(* Logix 5000 project; controller Test vendor 1 type 14 code 92 rev 33.11; software revision 33.00 *)

TASK MainTask (continuous, watchdog 500 ms) : MainProgram

MODULES
   Local : vendor 1 type 14 code 92 (ICP 0, rev 33.11)
      IN : vendor 1 type 7 code 1 (ICP 3, rev 3.2, Input RPI 20 ms)
      O : vendor 1 type 7 code 15 (ICP 2, rev 3.2, Output RPI 20 ms)
      Ethernet : 1756-ENBT (ICP 1, Ethernet 192.168.0.98, rev 6.4)
         IOLM1 : DXM (Ethernet 192.168.0.1, rev 2.22, StandardDataDriven RPI 20 ms)
END_MODULES

TYPE Banner_IOL_Port_v4 :   // UDT that has all of the data items necessary to communicate with a specific Port on a IO-Link Master
STRUCT
   Port_Controlled : INT;   // Each bit represents a port on an IO-Link Master. Set to 1 to tell AOI to control that port.
   Port_Activate : INT;   // Each bit represents a port on an IO-Link Master. When ON that port will process any commands in queue.
   Port_Read : INT;   // Each bit represents a port on an IO-Link Master. Used to determine when device AOI has requested a Read command.
   Port_Write : INT;   // Each bit represents a port on an IO-Link Master. Used to determine when device AOI has requested a Write command.
   Port_RW_Complete : INT;   // Each bit represents a port on an IO-Link Master. Tells device AOI that Read or Write request has been completed.
   Port_Device_Read : INT;
   Data_Transfer : SINT[190];   // Array to transfer data from IO-Master to device AOIs.
END_STRUCT
END_TYPE

TYPE Banner_IOLM_EL_v2 :   // Error Log for Messages to IOLM.
STRUCT
   RW : SINT;   // 0 = Read, 1 = Write.
   Port : SINT;   // Port number that generated error.
   Index : INT;   // IO-Link Index for generated error.
END_STRUCT
END_TYPE

TYPE Banner_IOLM_v4 :   // UDT to control IO-Link Masters.
STRUCT
   Message_Source_Data : SINT[190];
   Message_Destination_Data : SINT[190];
   Error_Log : Banner_IOLM_EL_v2[10];
   Error_Write_Retry : BOOL;
   Num_Error_MSGS : DINT;
   IO_Link_Master_Busy : BOOL;   // 0 = While waiting for a command, 1 = Processing command
   AOI_Reset : BOOL;
   Port_Data : Banner_IOL_Port_v4;   // All of the necessary data to work with the various ports of the IO-Link Master.
   Halt_Operation : BOOL;   // When parameter is 1 the AOI is halted as next available time frame.
   AOI_Halted : BOOL;   // AOI is in standby mode until Halt Operation tag is set back to 0.
END_STRUCT
END_TYPE

TYPE Banner_K50Z_BDC_v4 :   // All of the BDC data for channels 1 and 2.
STRUCT
   SP1 : DINT;   // Switchpoint.
   SP2 : DINT;   // In 2pt window mode, defines the second switching point. In other modes, SP2 is unused and must be 0.
   Switchpoint_Logic : SINT;   // 0 = Light operate, 1 = Dark operate
   BDC_Mode : INT;   // 1 = 1pt Object Set, 128 = 2pt static BGS, 129 = 2pt Window FGS, 130 = 1pt Window FGS, 131 = Dual Mode.
   Hysteresis : INT;   // A value of 0 will result in automatically calculated hysteresis.
   Delay_Mode : SINT;   // 0 = Disabled, 1 = On Off Delay, 2 = Oneshot.
   Delay_Time_On_Oneshot : DINT;   // 0 to 90000. On delay and oneshot time.
   Delay_Time_Off : DINT;   // 0 to 90000. Off delay only.
   Teach_Offset : SINT;   // 0 = Auto, 1 = User Selected
   User_Teach_Offset : DINT;   // In Object Set or Window (FGS) mode this value can be either positive or negative. In all other modes must be zero.
END_STRUCT
END_TYPE

TYPE Banner_K50Z_PD0_v4 :   // Process Data 0 for a K50Z.
STRUCT
   C1_Output_State : SINT;   // 0 = Inactive, 1 = Active
   C2_Output_State : SINT;   // 0 = Inactive, 1 = Active
   Stability_Z1 : SINT;   // 0 = No target or Marginal, 1 = Stable
   Stability_Z2 : SINT;   // 0 = No target or Marginal, 1 = Stable
   Measurement_1 : DINT;   // Default setting is Measurement Value for Zone 1. See IODD for all options.
   Measurement_2 : DINT;   // Default setting is Measurement Value for Zone 2. See IODD for all options.
END_STRUCT
END_TYPE

TYPE Banner_K50Z_PD1_v4 :   // Process Data 1 for a K50Z.
STRUCT
   Measurement_1 : DINT;   // Default setting is Measurement Value for Zone 1. See IODD for all options.
   Measurement_2 : DINT;   // Default setting is Measurement Value for Zone 2. See IODD for all options.
END_STRUCT
END_TYPE

TYPE Banner_K50Z_PD2_v4 :   // Process Data 2 for a K50Z.
STRUCT
   Measurement : DINT;   // Measurement Value
   Measure_Scale : DINT;   // Scale Factor for Measurement
   Stability : SINT;   // 0 = Inactive 1 = Active
   Channel_1 : SINT;   // 0 = Inactive 1 = Active
   Channel_2 : INT;   // 0 = Inactive 1 = Active
END_STRUCT
END_TYPE

TYPE Banner_K50Z_PDIO_v4 :   // Process Data for a K50Z.
STRUCT
   PDI_0 : Banner_K50Z_PD0_v4;   // Input Procoess Data for Configuration 0
   PDI_1 : Banner_K50Z_PD1_v4;   // Input Procoess Data for Configuration 1
   PDI_2 : Banner_K50Z_PD2_v4;   // Input Procoess Data for Configuration 2
   Emitter_Disable : SINT;   // 0 = Active 1 = Inactive
   PDI_DT : SINT[4];
END_STRUCT
END_TYPE

TYPE Banner_K50Z_Pulse_Freq_v4 :
STRUCT
   Near_Freq : DINT;   // 1 to 100000 in Hz
   Far_Freq : DINT;   // 1 to 100000 in Hz
   SP1 : DINT;   // Switchpoint
   SP2 : DINT;   // In 2pt Window FGS teach, define the second switching point. In other modes SP2 should be zero.
   Pulse_Freq_LOS : DINT;   // Default value of 50. This is the Hz that the units outputs when a Loss of Signal occurs.
END_STRUCT
END_TYPE

TYPE Banner_K50Z_RD_v4 :   // UDT that stores the Write Data for a K50Z.
STRUCT
   Master_Cycle_Time : INT;
   Min_Cycle_Time : INT;
   M_Sequence_Capability : INT;
   IO_Link_Version_ID : INT;
   Process_Data_Input_Length : INT;
   Process_Data_Output_Length : INT;
   Combined_Vendor_ID : DINT;   // IO-Link Vendor ID
   Vendor_ID1 : INT;
   Vendor_ID2 : INT;
   Combined_Device_ID : DINT;   // IO-Link Device ID
   Device_ID1 : INT;
   Device_ID2 : INT;
   Device_ID3 : INT;
   Serial_Number : STRING;
   Teach_State : SINT;   // 0=Idle, 1=SP1 Success, 4=Wait for Command, 5=Busy, 7=Error.
   SP1_TP1 : SINT;
   SP1_TP2 : SINT;
   Measurement_Z1 : DINT;
   Excess_Gain_Z1 : DINT;   // Amount of singal measured over the minimum threshold.
   Stability_Z1 : SINT;   // 0=No target exists, 1=Marginal signal, 2=Stable.
   Measurement_Z2 : DINT;
   Excess_Gain_Z2 : DINT;   // Amount of singal measured over the minimum threshold.
   Stability_Z2 : SINT;   // 0=No target exists, 1=Marginal signal, 2=Stable.
   Emitter_Status : SINT;   // 0 = Active, 1 = Inactive
   Temperature : DINT;   // Internal temperature measurement for the device.
   Last_Taught_Temperature : DINT;   // Internal Temperature the last time device was taught.
   MDC_Lower_Limit : DINT;
   MDC_Upper_Limit : DINT;
   MDC_Unit : INT;
   MDC_Scale : SINT;
END_STRUCT
END_TYPE

TYPE Banner_K50Z_v4 :   // All of the parameters for a K50Z.
STRUCT
   Initial_Global_Read : BOOL;   // Determines if all of the IO-Link data has been read into the PLC yet
   Command : INT;   // Value placed in here will activate a read or write to a specifc IO-Link Index
   Read : Banner_K50Z_RD_v4;   // Read Only Data
   Write : Banner_K50Z_WD_v4;   // Write Data
   Archive : Banner_K50Z_WD_v4;   // Archive Data
   Reset : BOOL;   // Resets AOI. This will force a complete parameter read of the sensor.
END_STRUCT
END_TYPE

TYPE Banner_K50Z_WD_v4 :   // UDT that stores the Write Data for a K50Z.
STRUCT
   System_Command : INT;   // See IODD file for list of commands that can be activated via the System Command interface
   Parameter_Access_Lock : SINT;   // Write access to all parameters is prohibited while value is 1. Only this parameter can be adjusted when value is 1.
   Data_Storage_Lock : SINT;   // Automatic data storage is disabled when this value is equal to 1. Read access is not affected.
   Local_Parameterization_Lock : SINT;   // Parameterization via local control elements on device is disabled.
   Local_User_Interface_Lock : SINT;   // Operation of local user interface is disabled.
   Teach_Channel : SINT;   // 0 = Default, 1 = BDC1, 2 = BDC2
   Response_Speed : SINT;   // 0 = Speed 0, 1 = Speed 1, 2 = Speed 2, 3 = Speed 3
   Remote_Input_Mode : SINT;   // 0 = Remote Teach Input, 1 = Emitter On, 2 = Emitter Off
   Secondary_Output_Mode : SINT;   // 0 = Independent Output, 1 = Complementary Output, 2 = Pulse Frequency Output
   IOL_Filter_Time : INT;   // Time to average IOl process data measurement between updates
   Include_Binary : SINT;   // 0 = Include, 1 = Don't Include, 2= Measurement Device
   Measurement_1 : SINT;   // 0 = Disabled, 1 = Excess Gain Z1, 2 = Excess Gain Z2, 3 = Excess Gain / 10 Z1, 4 = Excess Gain / 10 Z2, 5 = Measurement Z1, 6 = Measurement Z2.
   Measurement_2 : SINT;   // 0 = Disabled, 1 = Excess Gain Z1, 2 = Excess Gain Z2, 3 = Excess Gain / 10 Z1, 4 = Excess Gain / 10 Z2, 5 = Measurement Z1, 6 = Measurement Z2.
   Digital_Measuring_Sensor_Zone_Selection : SINT;   // 0=Zone 1, 1=Zone2
   BDC : Banner_K50Z_BDC_v4[3];
   Pulse_Freq : Banner_K50Z_Pulse_Freq_v4;
END_STRUCT
END_TYPE

ADD_ON_INSTRUCTION Banner_DXMR90_IOLM_v4   (* revision 4.1, vendor Banner Engineering *)
// AOI that controls a Banner IO-Link Master with Banner devices.
// Revision note:
// Revised operational order for ISDU write.
VAR_IN_OUT
   IOLM : Banner_IOLM_v4; {required}
END_VAR
VAR
   Lock : DINT; {access None}
   Byte_Length : SINT; {access None}
   Current_Port : INT; {access None}   // Current port to communicate with via the IO-Link Master.
   Timer : TIMER := (PRE := 500); {access None}
   Error_Index : DINT; {access None}
   Timer2 : TIMER := (PRE := 5000); {access None}
   Temp_Index : INT; {access None}
   ErrCount : DINT; {access None}
   Timer4 : TIMER := (PRE := 2000); {access None}
   Timer5 : TIMER := (PRE := 2000); {access None}
   Timer3 : TIMER := (PRE := 2000); {access None}
   Timer6 : TIMER := (PRE := 3000); {access None}
   Timer7 : TIMER := (PRE := 3000); {access None}
END_VAR

ROUTINE Logic   (* ladder *)
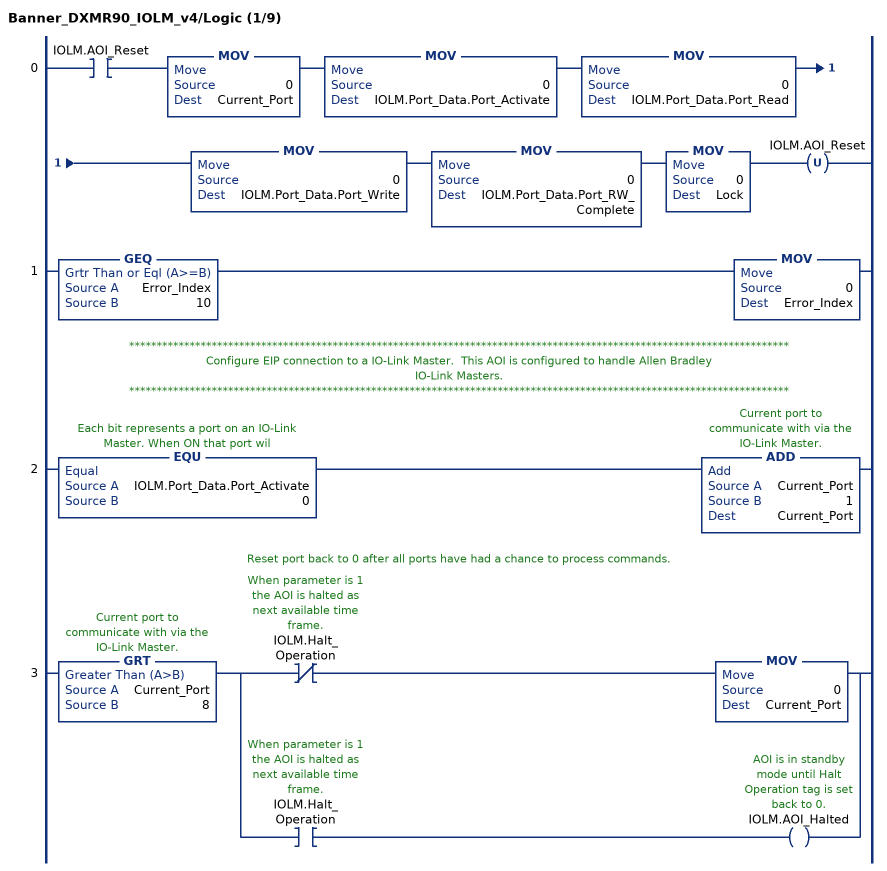
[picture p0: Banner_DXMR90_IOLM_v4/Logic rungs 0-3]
   0: XIC(IOLM.AOI_Reset)MOV(0,Current_Port)MOV(0,IOLM.Port_Data.Port_Activate)MOV(0,IOLM.Port_Data.Port_Read)MOV(0,IOLM.Port_Data.Port_Write)MOV(0,IOLM.Port_Data.Port_RW_Complete)MOV(0,Lock)OTU(IOLM.AOI_Reset);
   1: GEQ(Error_Index,10)MOV(0,Error_Index);
   // ************************************************************************************************************************
   // Configure EIP connection to a IO-Link Master.  This AOI is configured to handle Allen Bradley
   // IO-Link Masters.
   // ************************************************************************************************************************
   2: EQU(IOLM.Port_Data.Port_Activate,0)ADD(Current_Port,1,Current_Port);
   // Reset port back to 0 after all ports have had a chance to process commands.
   3: GRT(Current_Port,8)[XIO(IOLM.Halt_Operation) MOV(0,Current_Port) ,XIC(IOLM.Halt_Operation) OTE(IOLM.AOI_Halted) ];
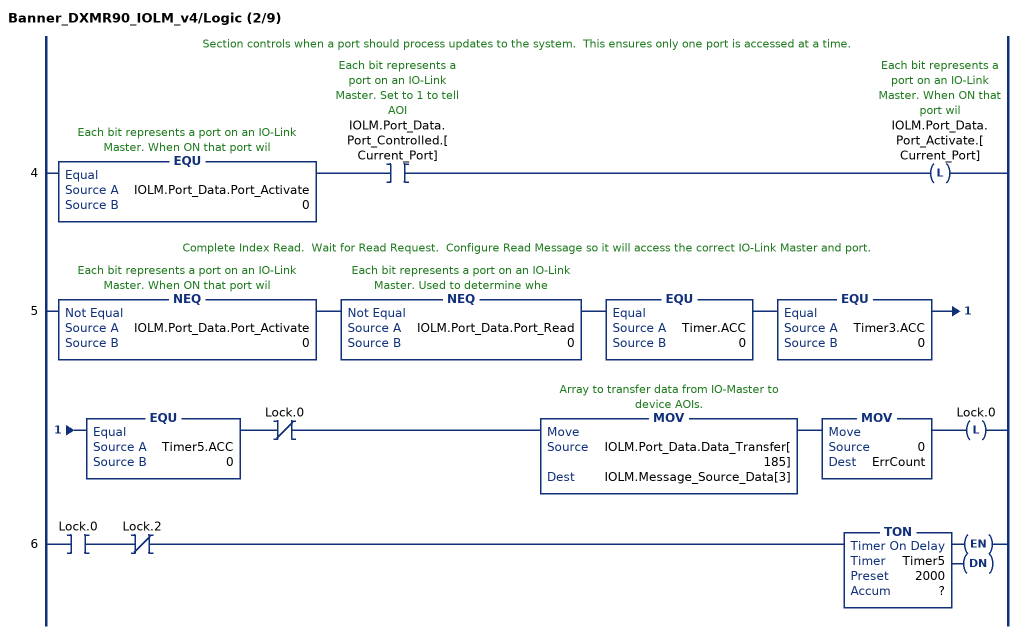
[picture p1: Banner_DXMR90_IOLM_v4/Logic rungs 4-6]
   // Section controls when a port should process updates to the system.  This ensures only one port is accessed at a time.
   4: EQU(IOLM.Port_Data.Port_Activate,0)XIC(IOLM.Port_Data.Port_Controlled.[Current_Port])OTL(IOLM.Port_Data.Port_Activate.[Current_Port]);
   // Complete Index Read.  Wait for Read Request.  Configure Read Message so it will access the correct IO-Link Master and port.
   5: NEQ(IOLM.Port_Data.Port_Activate,0)NEQ(IOLM.Port_Data.Port_Read,0)EQU(Timer.ACC,0)EQU(Timer3.ACC,0)EQU(Timer5.ACC,0)XIO(Lock.0)MOV(IOLM.Port_Data.Data_Transfer[185],IOLM.Message_Source_Data[3])MOV(0,ErrCount)OTL(Lock.0);
   6: XIC(Lock.0)XIO(Lock.2)TON(Timer5,?,?);
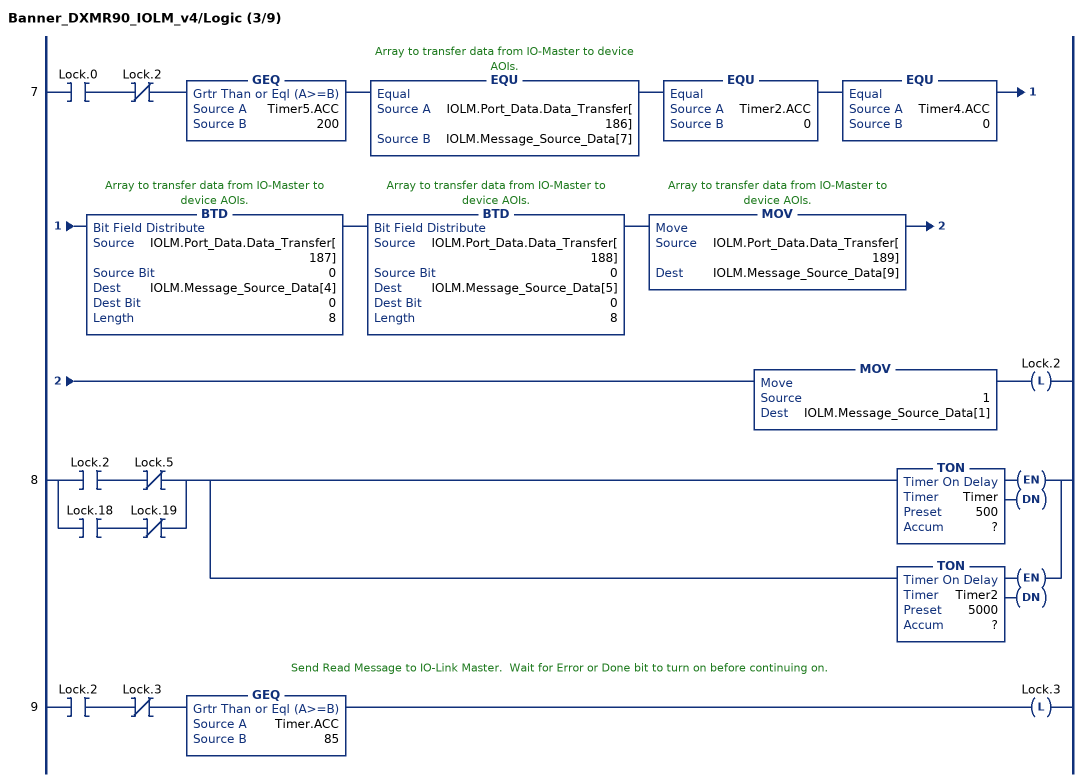
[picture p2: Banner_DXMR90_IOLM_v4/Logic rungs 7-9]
   7: XIC(Lock.0)XIO(Lock.2)GEQ(Timer5.ACC,200)EQU(IOLM.Port_Data.Data_Transfer[186],IOLM.Message_Source_Data[7])EQU(Timer2.ACC,0)EQU(Timer4.ACC,0)BTD(IOLM.Port_Data.Data_Transfer[187],0,IOLM.Message_Source_Data[4],0,8)BTD(IOLM.Port_Data.Data_Transfer[188],0,IOLM.Message_Source_Data[5],0,8)MOV(IOLM.Port_Data.Data_Transfer[189],IOLM.Message_Source_Data[9])MOV(1,IOLM.Message_Source_Data[1])OTL(Lock.2);
   8: [XIC(Lock.2) XIO(Lock.5) ,XIC(Lock.18) XIO(Lock.19) ][TON(Timer,?,?) ,TON(Timer2,?,?) ];
   // Send Read Message to IO-Link Master.  Wait for Error or Done bit to turn on before continuing on.
   9: XIC(Lock.2)XIO(Lock.3)GEQ(Timer.ACC,85)OTL(Lock.3);
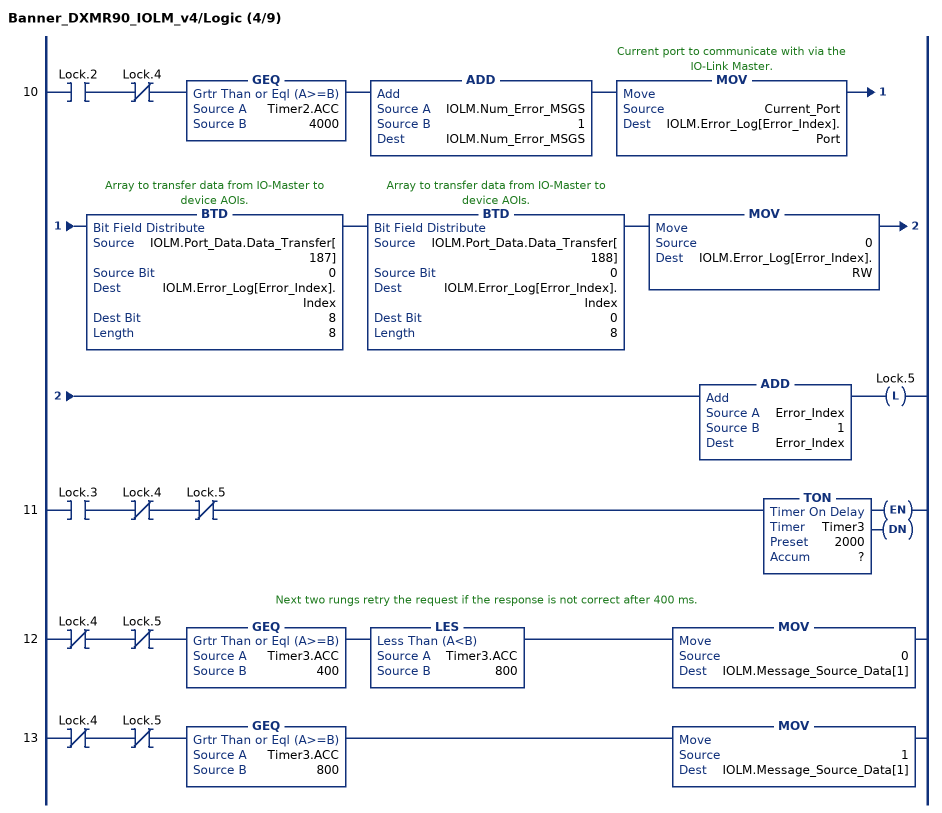
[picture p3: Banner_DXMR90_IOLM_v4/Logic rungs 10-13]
   10: XIC(Lock.2)XIO(Lock.4)GEQ(Timer2.ACC,4000)ADD(IOLM.Num_Error_MSGS,1,IOLM.Num_Error_MSGS)MOV(Current_Port,IOLM.Error_Log[Error_Index].Port)BTD(IOLM.Port_Data.Data_Transfer[187],0,IOLM.Error_Log[Error_Index].Index,8,8)BTD(IOLM.Port_Data.Data_Transfer[188],0,IOLM.Error_Log[Error_Index].Index,0,8)MOV(0,IOLM.Error_Log[Error_Index].RW)ADD(Error_Index,1,Error_Index)OTL(Lock.5);
   11: XIC(Lock.3)XIO(Lock.4)XIO(Lock.5)TON(Timer3,?,?);
   // Next two rungs retry the request if the response is not correct after 400 ms.
   12: XIO(Lock.4)XIO(Lock.5)GEQ(Timer3.ACC,400)LES(Timer3.ACC,800)MOV(0,IOLM.Message_Source_Data[1]);
   13: XIO(Lock.4)XIO(Lock.5)GEQ(Timer3.ACC,800)MOV(1,IOLM.Message_Source_Data[1]);
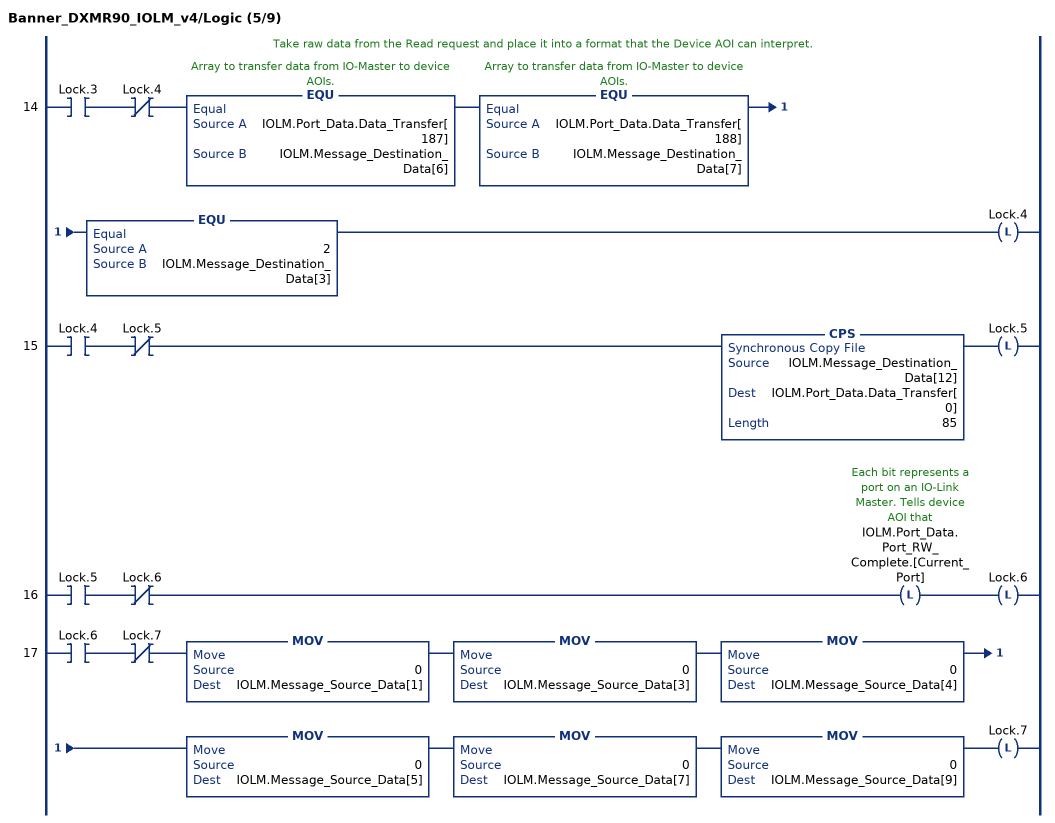
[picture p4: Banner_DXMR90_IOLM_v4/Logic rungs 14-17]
   // Take raw data from the Read request and place it into a format that the Device AOI can interpret.
   14: XIC(Lock.3)XIO(Lock.4)EQU(IOLM.Port_Data.Data_Transfer[187],IOLM.Message_Destination_Data[6])EQU(IOLM.Port_Data.Data_Transfer[188],IOLM.Message_Destination_Data[7])EQU(2,IOLM.Message_Destination_Data[3])OTL(Lock.4);
   15: XIC(Lock.4)XIO(Lock.5)CPS(IOLM.Message_Destination_Data[12],IOLM.Port_Data.Data_Transfer[0],85)OTL(Lock.5);
   16: XIC(Lock.5)XIO(Lock.6)OTL(IOLM.Port_Data.Port_RW_Complete.[Current_Port])OTL(Lock.6);
   17: XIC(Lock.6)XIO(Lock.7)MOV(0,IOLM.Message_Source_Data[1])MOV(0,IOLM.Message_Source_Data[3])MOV(0,IOLM.Message_Source_Data[4])MOV(0,IOLM.Message_Source_Data[5])MOV(0,IOLM.Message_Source_Data[7])MOV(0,IOLM.Message_Source_Data[9])OTL(Lock.7);
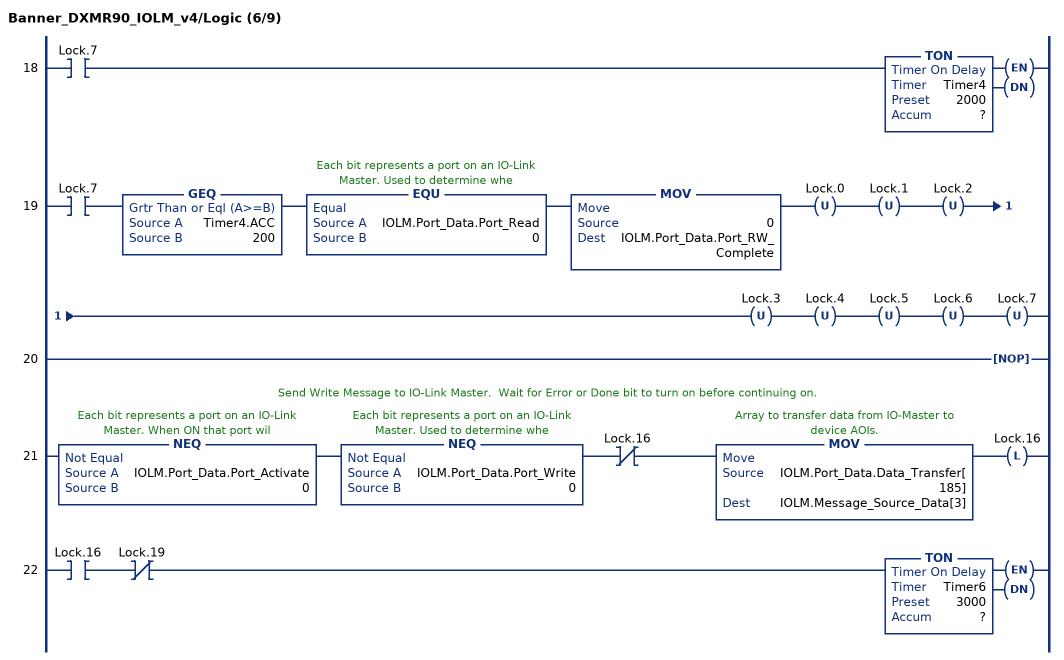
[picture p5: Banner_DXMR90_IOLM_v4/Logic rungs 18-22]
   18: XIC(Lock.7)TON(Timer4,?,?);
   19: XIC(Lock.7)GEQ(Timer4.ACC,200)EQU(IOLM.Port_Data.Port_Read,0)MOV(0,IOLM.Port_Data.Port_RW_Complete)OTU(Lock.0)OTU(Lock.1)OTU(Lock.2)OTU(Lock.3)OTU(Lock.4)OTU(Lock.5)OTU(Lock.6)OTU(Lock.7);
   20: NOP();
   // Send Write Message to IO-Link Master.  Wait for Error or Done bit to turn on before continuing on.
   21: NEQ(IOLM.Port_Data.Port_Activate,0)NEQ(IOLM.Port_Data.Port_Write,0)XIO(Lock.16)MOV(IOLM.Port_Data.Data_Transfer[185],IOLM.Message_Source_Data[3])OTL(Lock.16);
   22: XIC(Lock.16)XIO(Lock.19)TON(Timer6,?,?);
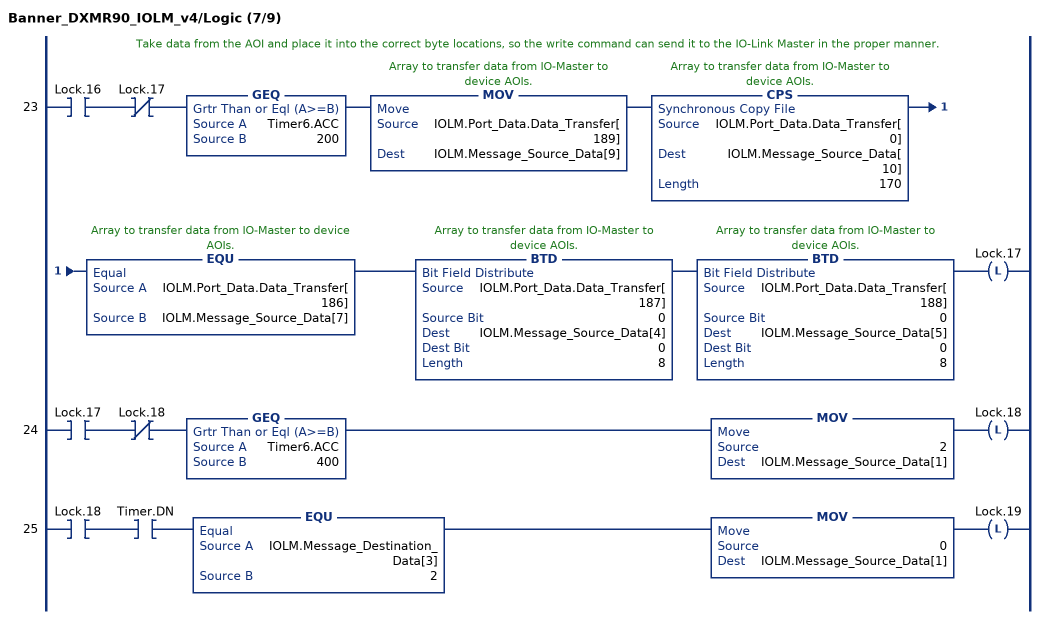
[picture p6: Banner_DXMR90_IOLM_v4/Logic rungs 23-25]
   // Take data from the AOI and place it into the correct byte locations, so the write command can send it to the IO-Link Master in the proper manner.
   23: XIC(Lock.16)XIO(Lock.17)GEQ(Timer6.ACC,200)MOV(IOLM.Port_Data.Data_Transfer[189],IOLM.Message_Source_Data[9])CPS(IOLM.Port_Data.Data_Transfer[0],IOLM.Message_Source_Data[10],170)EQU(IOLM.Port_Data.Data_Transfer[186],IOLM.Message_Source_Data[7])BTD(IOLM.Port_Data.Data_Transfer[187],0,IOLM.Message_Source_Data[4],0,8)BTD(IOLM.Port_Data.Data_Transfer[188],0,IOLM.Message_Source_Data[5],0,8)OTL(Lock.17);
   24: XIC(Lock.17)XIO(Lock.18)GEQ(Timer6.ACC,400)MOV(2,IOLM.Message_Source_Data[1])OTL(Lock.18);
   25: XIC(Lock.18)XIC(Timer.DN)EQU(IOLM.Message_Destination_Data[3],2)MOV(0,IOLM.Message_Source_Data[1])OTL(Lock.19);
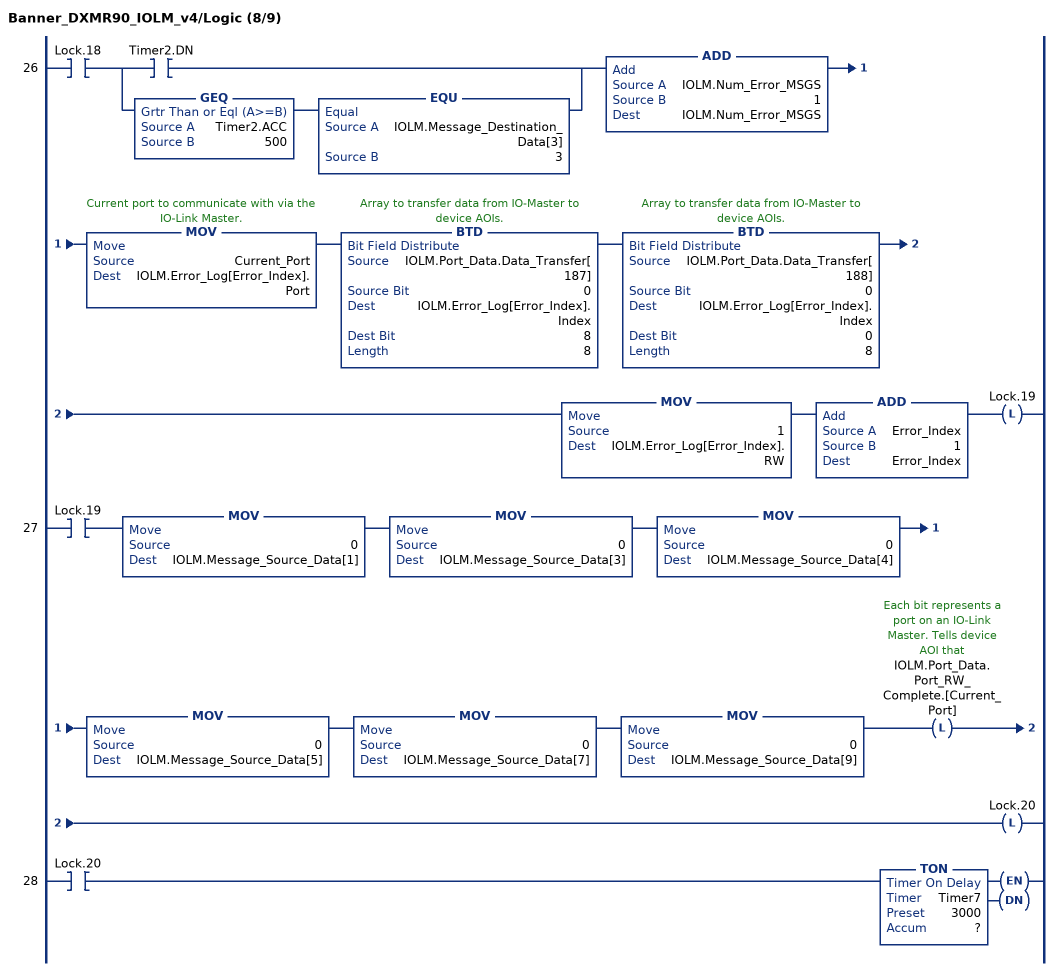
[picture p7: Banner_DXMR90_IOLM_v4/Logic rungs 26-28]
   26: XIC(Lock.18)[XIC(Timer2.DN) ,GEQ(Timer2.ACC,500) EQU(IOLM.Message_Destination_Data[3],3) ]ADD(IOLM.Num_Error_MSGS,1,IOLM.Num_Error_MSGS)MOV(Current_Port,IOLM.Error_Log[Error_Index].Port)BTD(IOLM.Port_Data.Data_Transfer[187],0,IOLM.Error_Log[Error_Index].Index,8,8)BTD(IOLM.Port_Data.Data_Transfer[188],0,IOLM.Error_Log[Error_Index].Index,0,8)MOV(1,IOLM.Error_Log[Error_Index].RW)ADD(Error_Index,1,Error_Index)OTL(Lock.19);
   27: XIC(Lock.19)MOV(0,IOLM.Message_Source_Data[1])MOV(0,IOLM.Message_Source_Data[3])MOV(0,IOLM.Message_Source_Data[4])MOV(0,IOLM.Message_Source_Data[5])MOV(0,IOLM.Message_Source_Data[7])MOV(0,IOLM.Message_Source_Data[9])OTL(IOLM.Port_Data.Port_RW_Complete.[Current_Port])OTL(Lock.20);
   28: XIC(Lock.20)TON(Timer7,?,?);
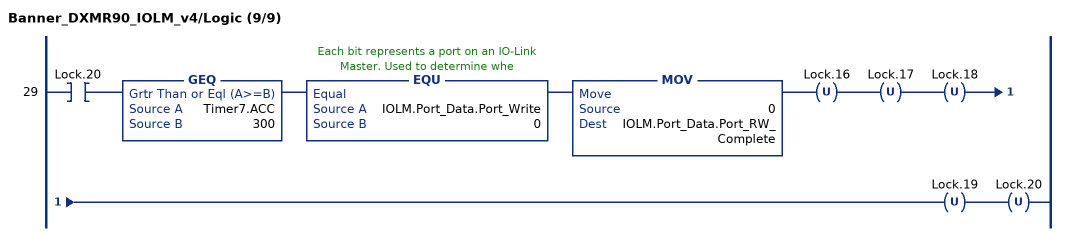
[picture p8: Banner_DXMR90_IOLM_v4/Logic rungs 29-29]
   29: XIC(Lock.20)GEQ(Timer7.ACC,300)EQU(IOLM.Port_Data.Port_Write,0)MOV(0,IOLM.Port_Data.Port_RW_Complete)OTU(Lock.16)OTU(Lock.17)OTU(Lock.18)OTU(Lock.19)OTU(Lock.20);
END_ROUTINE
END_ADD_ON_INSTRUCTION

ADD_ON_INSTRUCTION Banner_K50Z_Param_v4   (* revision 4.1, vendor Banner Engineering *)
// AOI to read and write parameter data to an IO-Link K50Z.
VAR_IN_OUT
   K50Z : Banner_K50Z_v4; {required}
   Port_Data : Banner_IOL_Port_v4; {required}
END_VAR
VAR_INPUT
   Port : DINT; {required}
END_VAR
VAR
   Local_Control : DINT; {access None}
   Global_Read_Command_Value : INT; {access None}
   Global_Write_Command_Value : INT; {access None}
   Command_Being_Processed : BOOL; {access None}
   Update_Archive : BOOL; {access None}
   Index_Write_Inprocess : INT; {access None}
   Index_Write_Control : INT; {access None}
   Inprocess_Index : DINT; {access None}
END_VAR

ROUTINE Logic   (* ladder *)
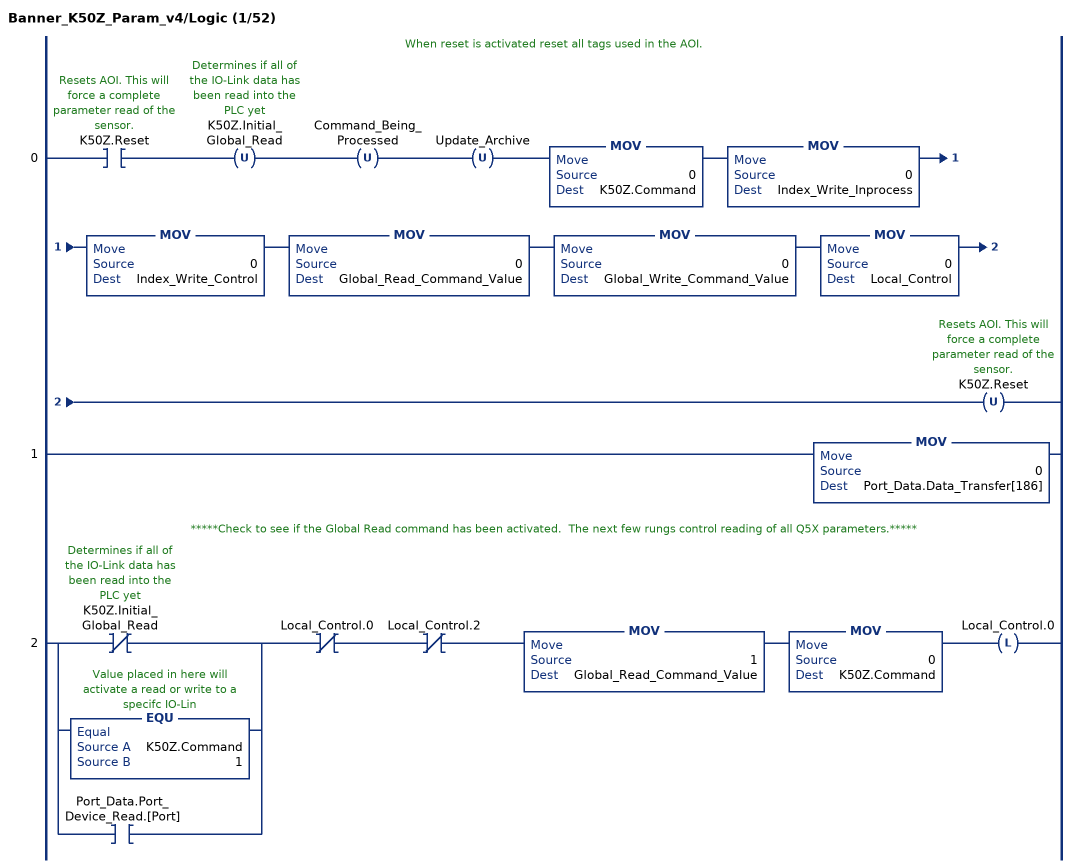
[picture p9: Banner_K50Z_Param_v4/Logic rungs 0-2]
   // When reset is activated reset all tags used in the AOI.
   0: XIC(K50Z.Reset)OTU(K50Z.Initial_Global_Read)OTU(Command_Being_Processed)OTU(Update_Archive)MOV(0,K50Z.Command)MOV(0,Index_Write_Inprocess)MOV(0,Index_Write_Control)MOV(0,Global_Read_Command_Value)MOV(0,Global_Write_Command_Value)MOV(0,Local_Control)OTU(K50Z.Reset);
   1: MOV(0,Port_Data.Data_Transfer[186]);
   // *****Check to see if the Global Read command has been activated.  The next few rungs control reading of all Q5X parameters.*****
   2: [XIO(K50Z.Initial_Global_Read) ,EQU(K50Z.Command,1) ,XIC(Port_Data.Port_Device_Read.[Port]) ]XIO(Local_Control.0)XIO(Local_Control.2)MOV(1,Global_Read_Command_Value)MOV(0,K50Z.Command)OTL(Local_Control.0);
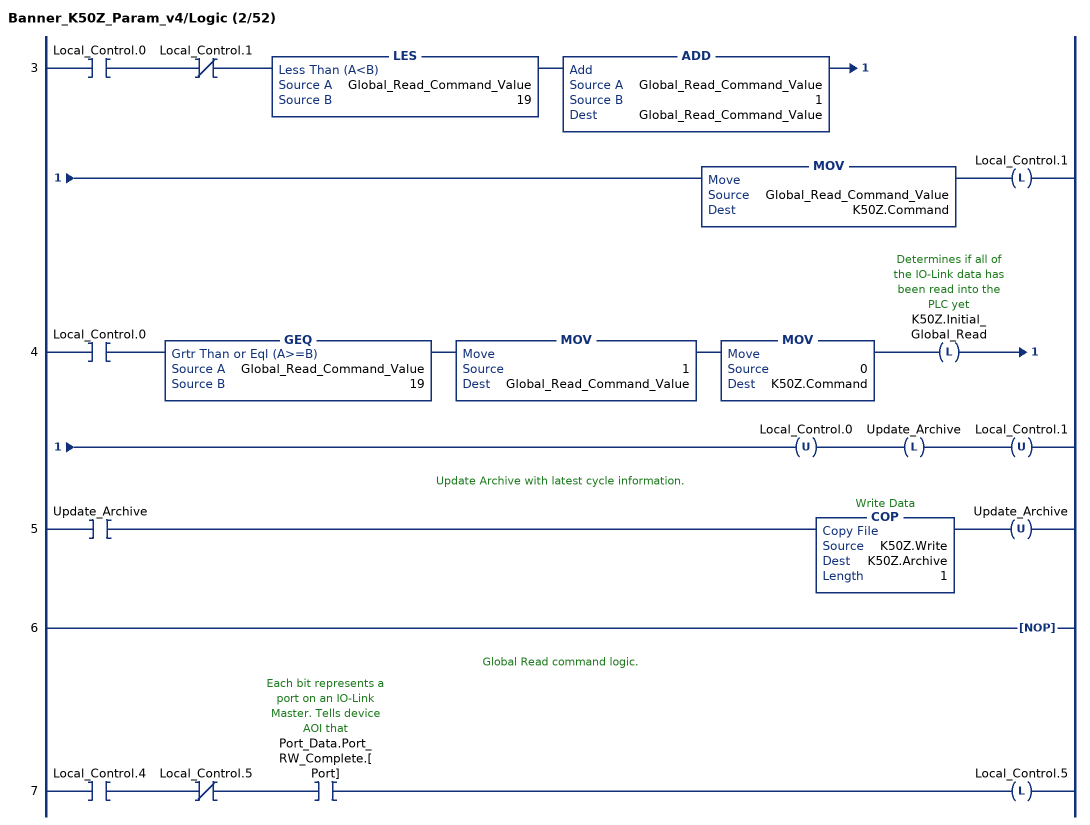
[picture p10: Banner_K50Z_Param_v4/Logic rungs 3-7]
   3: XIC(Local_Control.0)XIO(Local_Control.1)LES(Global_Read_Command_Value,19)ADD(Global_Read_Command_Value,1,Global_Read_Command_Value)MOV(Global_Read_Command_Value,K50Z.Command)OTL(Local_Control.1);
   4: XIC(Local_Control.0)GEQ(Global_Read_Command_Value,19)MOV(1,Global_Read_Command_Value)MOV(0,K50Z.Command)OTL(K50Z.Initial_Global_Read)OTU(Local_Control.0)OTL(Update_Archive)OTU(Local_Control.1);
   // Update Archive with latest cycle information.
   5: XIC(Update_Archive)COP(K50Z.Write,K50Z.Archive,1)OTU(Update_Archive);
   6: NOP();
   // Global Read command logic.
   7: XIC(Local_Control.4)XIO(Local_Control.5)XIC(Port_Data.Port_RW_Complete.[Port])OTL(Local_Control.5);
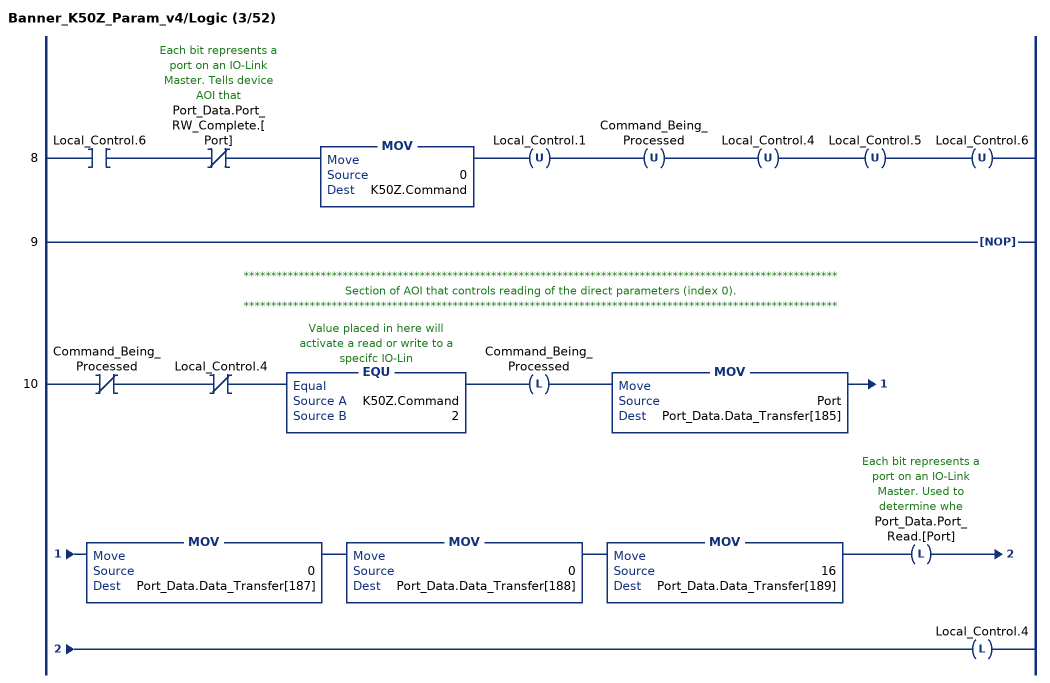
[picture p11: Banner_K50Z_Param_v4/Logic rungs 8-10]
   8: XIC(Local_Control.6)XIO(Port_Data.Port_RW_Complete.[Port])MOV(0,K50Z.Command)OTU(Local_Control.1)OTU(Command_Being_Processed)OTU(Local_Control.4)OTU(Local_Control.5)OTU(Local_Control.6);
   9: NOP();
   // ************************************************************************************************************
   // Section of AOI that controls reading of the direct parameters (index 0).
   // ************************************************************************************************************
   10: XIO(Command_Being_Processed)XIO(Local_Control.4)EQU(K50Z.Command,2)OTL(Command_Being_Processed)MOV(Port,Port_Data.Data_Transfer[185])MOV(0,Port_Data.Data_Transfer[187])MOV(0,Port_Data.Data_Transfer[188])MOV(16,Port_Data.Data_Transfer[189])OTL(Port_Data.Port_Read.[Port])OTL(Local_Control.4);
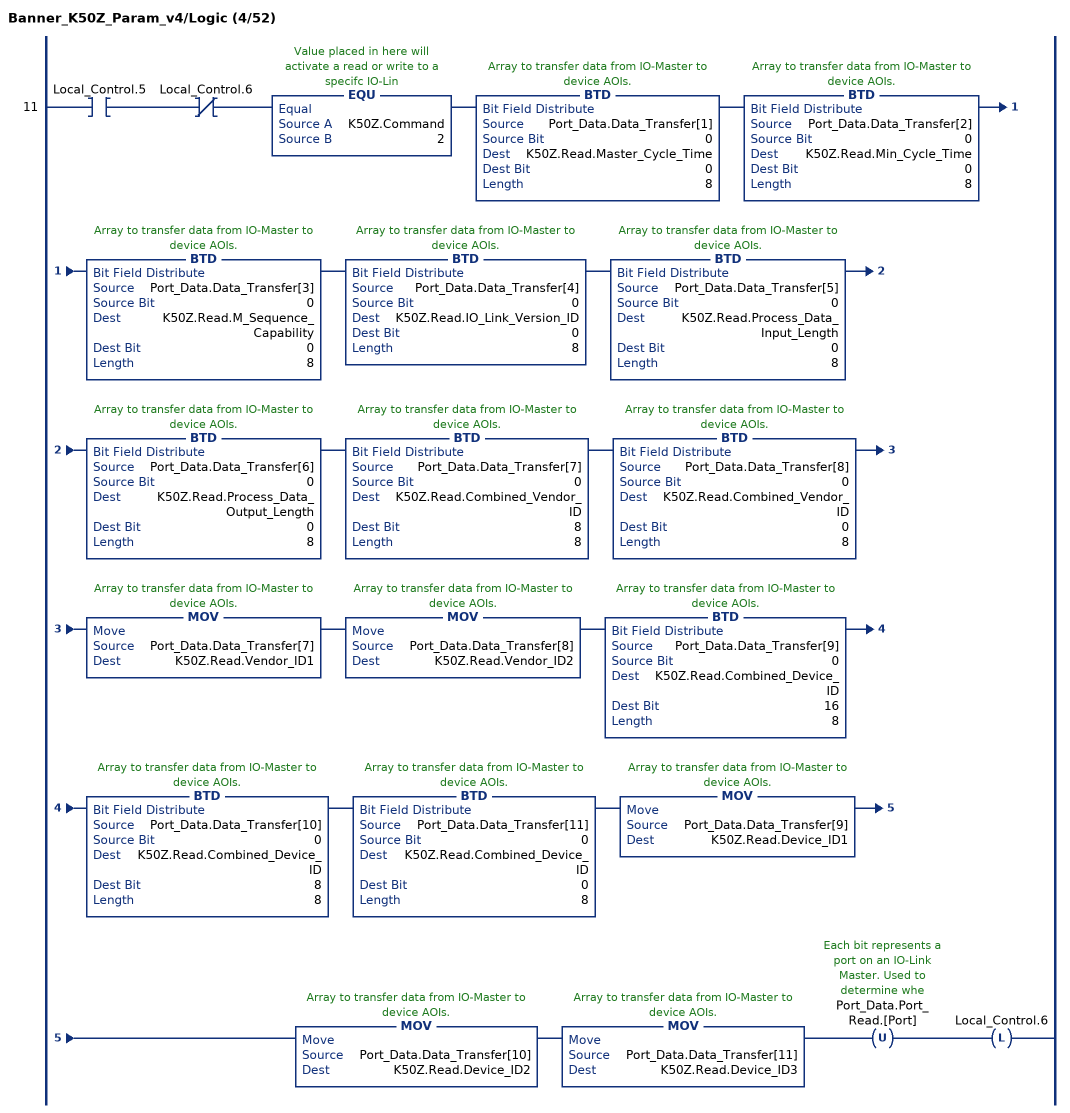
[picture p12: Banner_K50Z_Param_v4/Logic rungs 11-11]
   11: XIC(Local_Control.5)XIO(Local_Control.6)EQU(K50Z.Command,2)BTD(Port_Data.Data_Transfer[1],0,K50Z.Read.Master_Cycle_Time,0,8)BTD(Port_Data.Data_Transfer[2],0,K50Z.Read.Min_Cycle_Time,0,8)BTD(Port_Data.Data_Transfer[3],0,K50Z.Read.M_Sequence_Capability,0,8)BTD(Port_Data.Data_Transfer[4],0,K50Z.Read.IO_Link_Version_ID,0,8)BTD(Port_Data.Data_Transfer[5],0,K50Z.Read.Process_Data_Input_Length,0,8)BTD(Port_Data.Data_Transfer[6],0,K50Z.Read.Process_Data_Output_Length,0,8)BTD(Port_Data.Data_Transfer[7],0,K50Z.Read.Combined_Vendor_ID,8,8)BTD(Port_Data.Data_Transfer[8],0,K50Z.Read.Combined_Vendor_ID,0,8)MOV(Port_Data.Data_Transfer[7],K50Z.Read.Vendor_ID1)MOV(Port_Data.Data_Transfer[8],K50Z.Read.Vendor_ID2)BTD(Port_Data.Data_Transfer[9],0,K50Z.Read.Combined_Device_ID,16,8)BTD(Port_Data.Data_Transfer[10],0,K50Z.Read.Combined_Device_ID,8,8)BTD(Port_Data.Data_Transfer[11],0,K50Z.Read.Combined_Device_ID,0,8)MOV(Port_Data.Data_Transfer[9],K50Z.Read.Device_ID1)MOV(Port_Data.Data_Transfer[10],K50Z.Read.Device_ID2)MOV(Port_Data.Data_Transfer[11],K50Z.Read.Device_ID3)OTU(Port_Data.Port_Read.[Port])OTL(Local_Control.6);
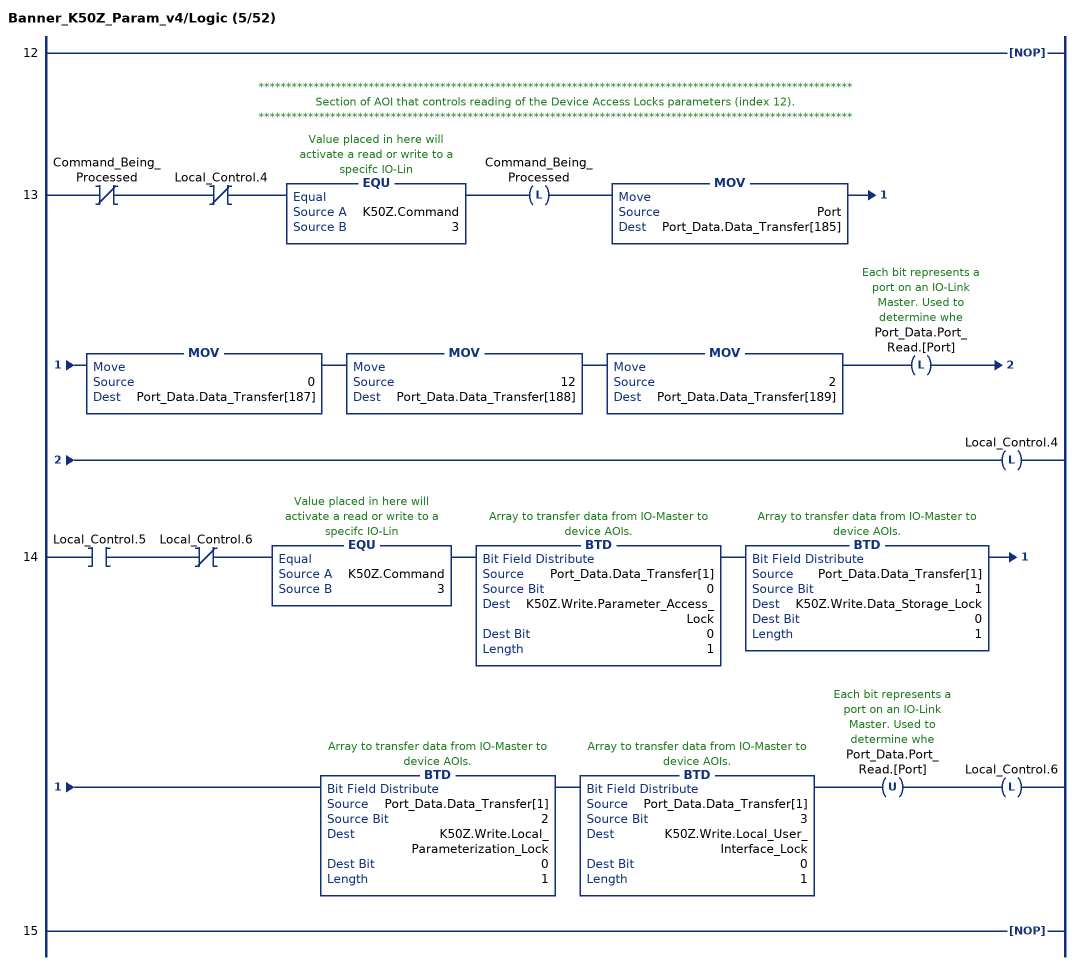
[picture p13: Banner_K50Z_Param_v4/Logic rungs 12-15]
   12: NOP();
   // ************************************************************************************************************
   // Section of AOI that controls reading of the Device Access Locks parameters (index 12).
   // ************************************************************************************************************
   13: XIO(Command_Being_Processed)XIO(Local_Control.4)EQU(K50Z.Command,3)OTL(Command_Being_Processed)MOV(Port,Port_Data.Data_Transfer[185])MOV(0,Port_Data.Data_Transfer[187])MOV(12,Port_Data.Data_Transfer[188])MOV(2,Port_Data.Data_Transfer[189])OTL(Port_Data.Port_Read.[Port])OTL(Local_Control.4);
   14: XIC(Local_Control.5)XIO(Local_Control.6)EQU(K50Z.Command,3)BTD(Port_Data.Data_Transfer[1],0,K50Z.Write.Parameter_Access_Lock,0,1)BTD(Port_Data.Data_Transfer[1],1,K50Z.Write.Data_Storage_Lock,0,1)BTD(Port_Data.Data_Transfer[1],2,K50Z.Write.Local_Parameterization_Lock,0,1)BTD(Port_Data.Data_Transfer[1],3,K50Z.Write.Local_User_Interface_Lock,0,1)OTU(Port_Data.Port_Read.[Port])OTL(Local_Control.6);
   15: NOP();
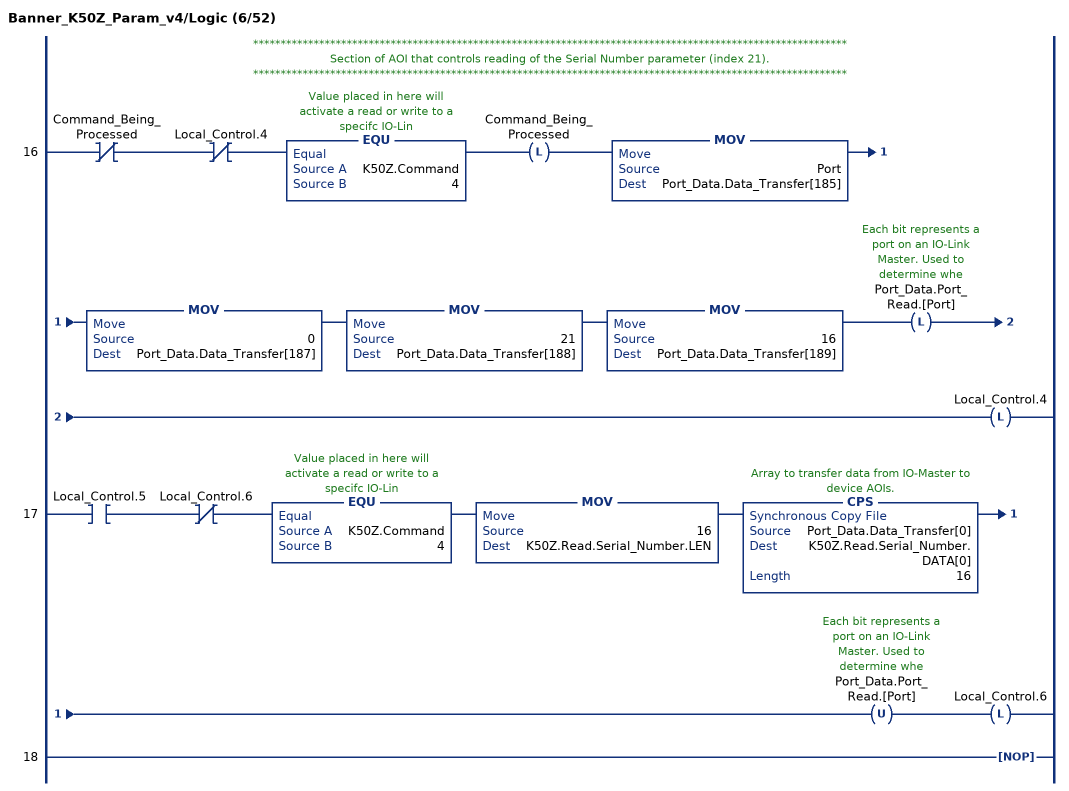
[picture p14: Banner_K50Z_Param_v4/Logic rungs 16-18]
   // ************************************************************************************************************
   // Section of AOI that controls reading of the Serial Number parameter (index 21).
   // ************************************************************************************************************
   16: XIO(Command_Being_Processed)XIO(Local_Control.4)EQU(K50Z.Command,4)OTL(Command_Being_Processed)MOV(Port,Port_Data.Data_Transfer[185])MOV(0,Port_Data.Data_Transfer[187])MOV(21,Port_Data.Data_Transfer[188])MOV(16,Port_Data.Data_Transfer[189])OTL(Port_Data.Port_Read.[Port])OTL(Local_Control.4);
   17: XIC(Local_Control.5)XIO(Local_Control.6)EQU(K50Z.Command,4)MOV(16,K50Z.Read.Serial_Number.LEN)CPS(Port_Data.Data_Transfer[0],K50Z.Read.Serial_Number.DATA[0],16)OTU(Port_Data.Port_Read.[Port])OTL(Local_Control.6);
   18: NOP();
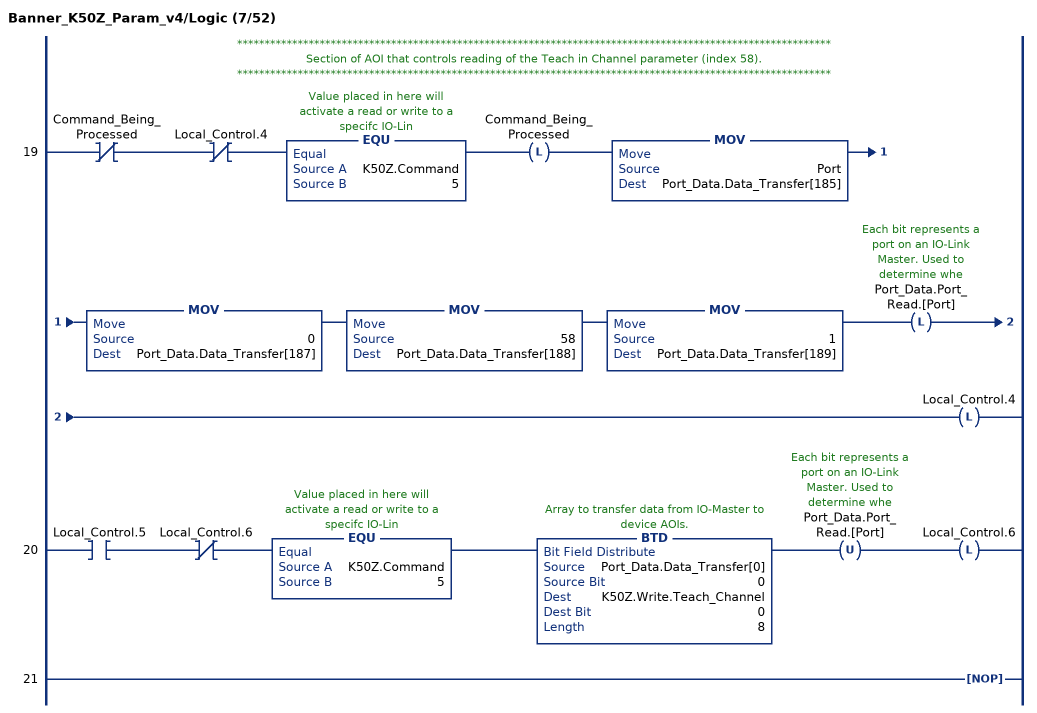
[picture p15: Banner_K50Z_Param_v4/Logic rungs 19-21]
   // ************************************************************************************************************
   // Section of AOI that controls reading of the Teach in Channel parameter (index 58).
   // ************************************************************************************************************
   19: XIO(Command_Being_Processed)XIO(Local_Control.4)EQU(K50Z.Command,5)OTL(Command_Being_Processed)MOV(Port,Port_Data.Data_Transfer[185])MOV(0,Port_Data.Data_Transfer[187])MOV(58,Port_Data.Data_Transfer[188])MOV(1,Port_Data.Data_Transfer[189])OTL(Port_Data.Port_Read.[Port])OTL(Local_Control.4);
   20: XIC(Local_Control.5)XIO(Local_Control.6)EQU(K50Z.Command,5)BTD(Port_Data.Data_Transfer[0],0,K50Z.Write.Teach_Channel,0,8)OTU(Port_Data.Port_Read.[Port])OTL(Local_Control.6);
   21: NOP();
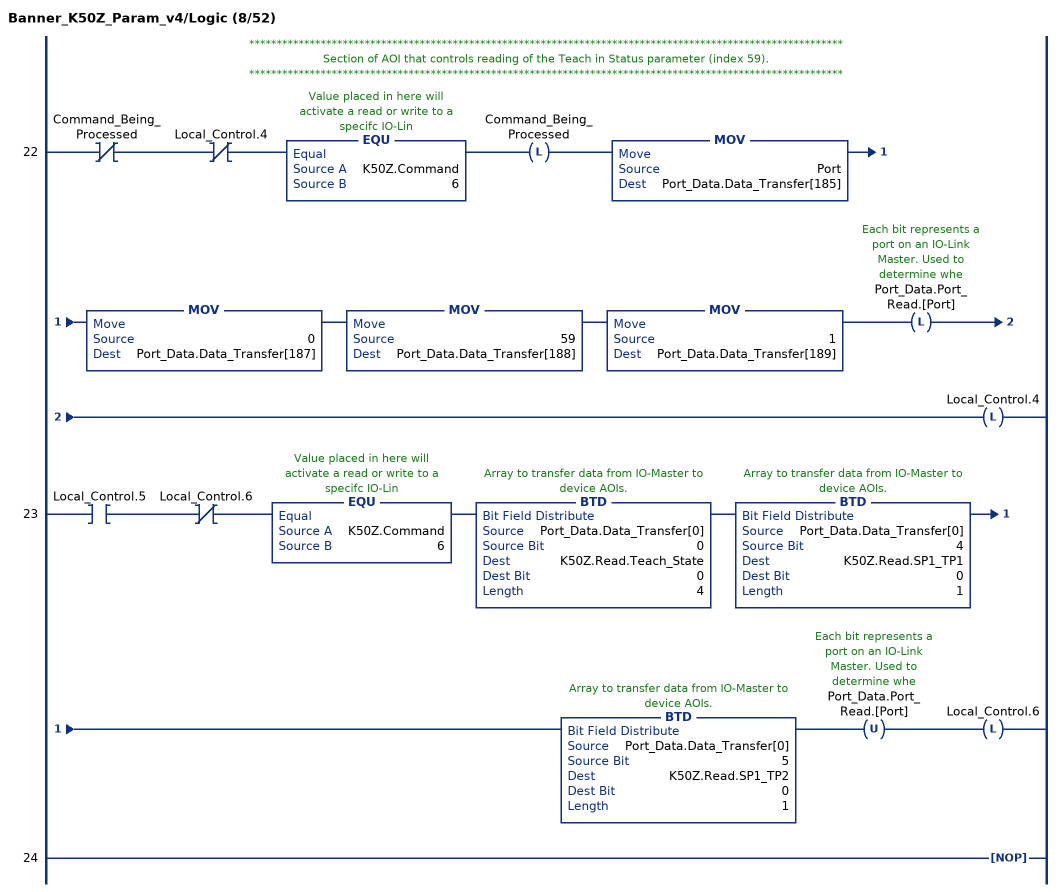
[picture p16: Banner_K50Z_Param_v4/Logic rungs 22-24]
   // ************************************************************************************************************
   // Section of AOI that controls reading of the Teach in Status parameter (index 59).
   // ************************************************************************************************************
   22: XIO(Command_Being_Processed)XIO(Local_Control.4)EQU(K50Z.Command,6)OTL(Command_Being_Processed)MOV(Port,Port_Data.Data_Transfer[185])MOV(0,Port_Data.Data_Transfer[187])MOV(59,Port_Data.Data_Transfer[188])MOV(1,Port_Data.Data_Transfer[189])OTL(Port_Data.Port_Read.[Port])OTL(Local_Control.4);
   23: XIC(Local_Control.5)XIO(Local_Control.6)EQU(K50Z.Command,6)BTD(Port_Data.Data_Transfer[0],0,K50Z.Read.Teach_State,0,4)BTD(Port_Data.Data_Transfer[0],4,K50Z.Read.SP1_TP1,0,1)BTD(Port_Data.Data_Transfer[0],5,K50Z.Read.SP1_TP2,0,1)OTU(Port_Data.Port_Read.[Port])OTL(Local_Control.6);
   24: NOP();
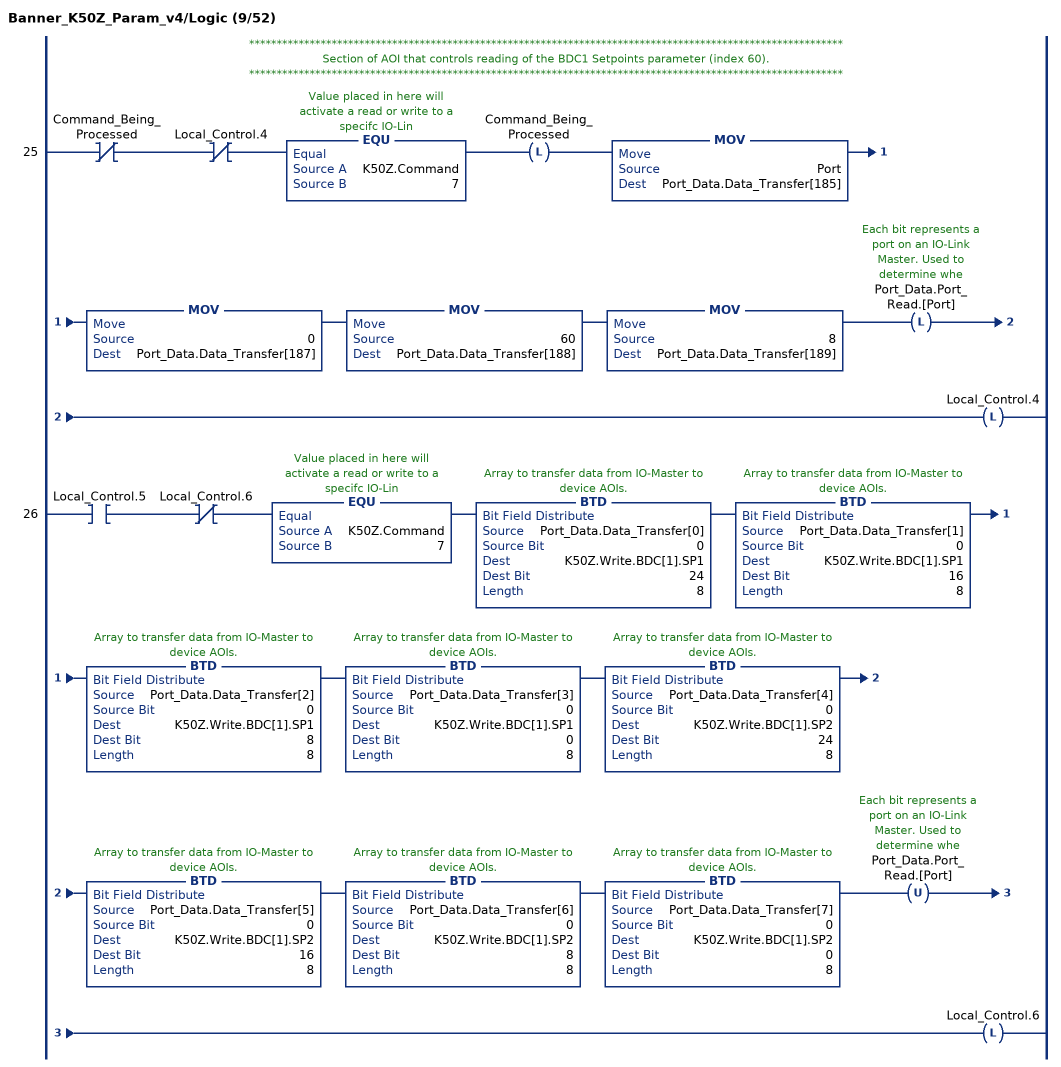
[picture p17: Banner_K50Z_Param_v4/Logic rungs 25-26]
   // ************************************************************************************************************
   // Section of AOI that controls reading of the BDC1 Setpoints parameter (index 60).
   // ************************************************************************************************************
   25: XIO(Command_Being_Processed)XIO(Local_Control.4)EQU(K50Z.Command,7)OTL(Command_Being_Processed)MOV(Port,Port_Data.Data_Transfer[185])MOV(0,Port_Data.Data_Transfer[187])MOV(60,Port_Data.Data_Transfer[188])MOV(8,Port_Data.Data_Transfer[189])OTL(Port_Data.Port_Read.[Port])OTL(Local_Control.4);
   26: XIC(Local_Control.5)XIO(Local_Control.6)EQU(K50Z.Command,7)BTD(Port_Data.Data_Transfer[0],0,K50Z.Write.BDC[1].SP1,24,8)BTD(Port_Data.Data_Transfer[1],0,K50Z.Write.BDC[1].SP1,16,8)BTD(Port_Data.Data_Transfer[2],0,K50Z.Write.BDC[1].SP1,8,8)BTD(Port_Data.Data_Transfer[3],0,K50Z.Write.BDC[1].SP1,0,8)BTD(Port_Data.Data_Transfer[4],0,K50Z.Write.BDC[1].SP2,24,8)BTD(Port_Data.Data_Transfer[5],0,K50Z.Write.BDC[1].SP2,16,8)BTD(Port_Data.Data_Transfer[6],0,K50Z.Write.BDC[1].SP2,8,8)BTD(Port_Data.Data_Transfer[7],0,K50Z.Write.BDC[1].SP2,0,8)OTU(Port_Data.Port_Read.[Port])OTL(Local_Control.6);
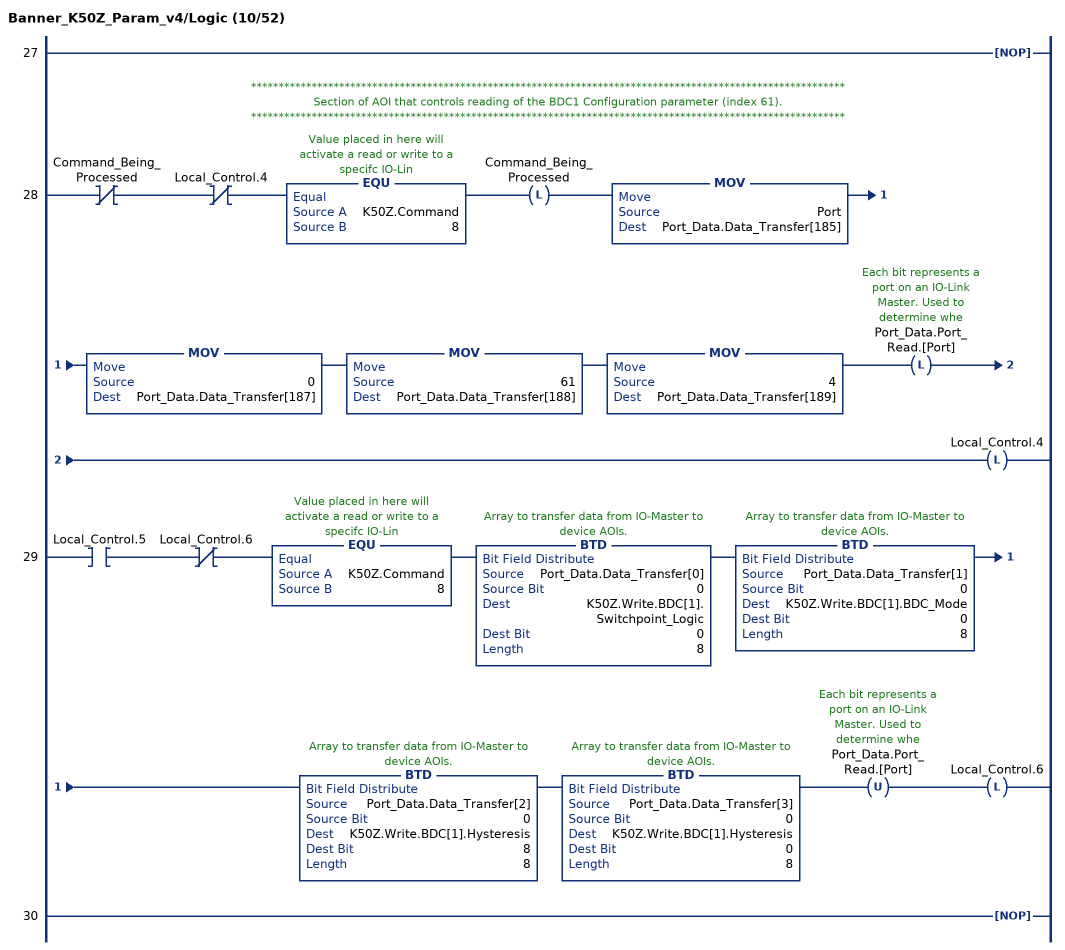
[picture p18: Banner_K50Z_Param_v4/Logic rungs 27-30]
   27: NOP();
   // ************************************************************************************************************
   // Section of AOI that controls reading of the BDC1 Configuration parameter (index 61).
   // ************************************************************************************************************
   28: XIO(Command_Being_Processed)XIO(Local_Control.4)EQU(K50Z.Command,8)OTL(Command_Being_Processed)MOV(Port,Port_Data.Data_Transfer[185])MOV(0,Port_Data.Data_Transfer[187])MOV(61,Port_Data.Data_Transfer[188])MOV(4,Port_Data.Data_Transfer[189])OTL(Port_Data.Port_Read.[Port])OTL(Local_Control.4);
   29: XIC(Local_Control.5)XIO(Local_Control.6)EQU(K50Z.Command,8)BTD(Port_Data.Data_Transfer[0],0,K50Z.Write.BDC[1].Switchpoint_Logic,0,8)BTD(Port_Data.Data_Transfer[1],0,K50Z.Write.BDC[1].BDC_Mode,0,8)BTD(Port_Data.Data_Transfer[2],0,K50Z.Write.BDC[1].Hysteresis,8,8)BTD(Port_Data.Data_Transfer[3],0,K50Z.Write.BDC[1].Hysteresis,0,8)OTU(Port_Data.Port_Read.[Port])OTL(Local_Control.6);
   30: NOP();
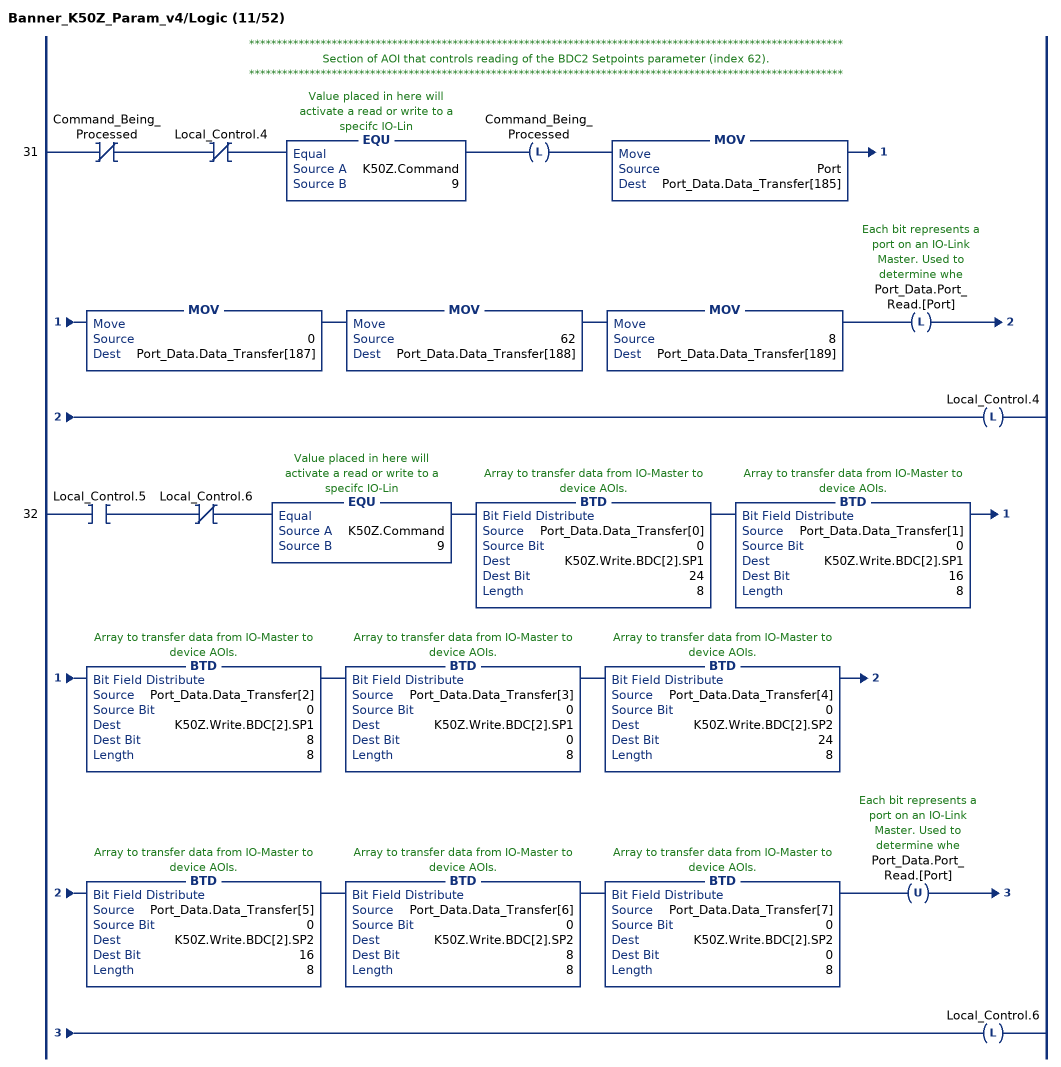
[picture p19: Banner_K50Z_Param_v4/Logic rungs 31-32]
   // ************************************************************************************************************
   // Section of AOI that controls reading of the BDC2 Setpoints parameter (index 62).
   // ************************************************************************************************************
   31: XIO(Command_Being_Processed)XIO(Local_Control.4)EQU(K50Z.Command,9)OTL(Command_Being_Processed)MOV(Port,Port_Data.Data_Transfer[185])MOV(0,Port_Data.Data_Transfer[187])MOV(62,Port_Data.Data_Transfer[188])MOV(8,Port_Data.Data_Transfer[189])OTL(Port_Data.Port_Read.[Port])OTL(Local_Control.4);
   32: XIC(Local_Control.5)XIO(Local_Control.6)EQU(K50Z.Command,9)BTD(Port_Data.Data_Transfer[0],0,K50Z.Write.BDC[2].SP1,24,8)BTD(Port_Data.Data_Transfer[1],0,K50Z.Write.BDC[2].SP1,16,8)BTD(Port_Data.Data_Transfer[2],0,K50Z.Write.BDC[2].SP1,8,8)BTD(Port_Data.Data_Transfer[3],0,K50Z.Write.BDC[2].SP1,0,8)BTD(Port_Data.Data_Transfer[4],0,K50Z.Write.BDC[2].SP2,24,8)BTD(Port_Data.Data_Transfer[5],0,K50Z.Write.BDC[2].SP2,16,8)BTD(Port_Data.Data_Transfer[6],0,K50Z.Write.BDC[2].SP2,8,8)BTD(Port_Data.Data_Transfer[7],0,K50Z.Write.BDC[2].SP2,0,8)OTU(Port_Data.Port_Read.[Port])OTL(Local_Control.6);
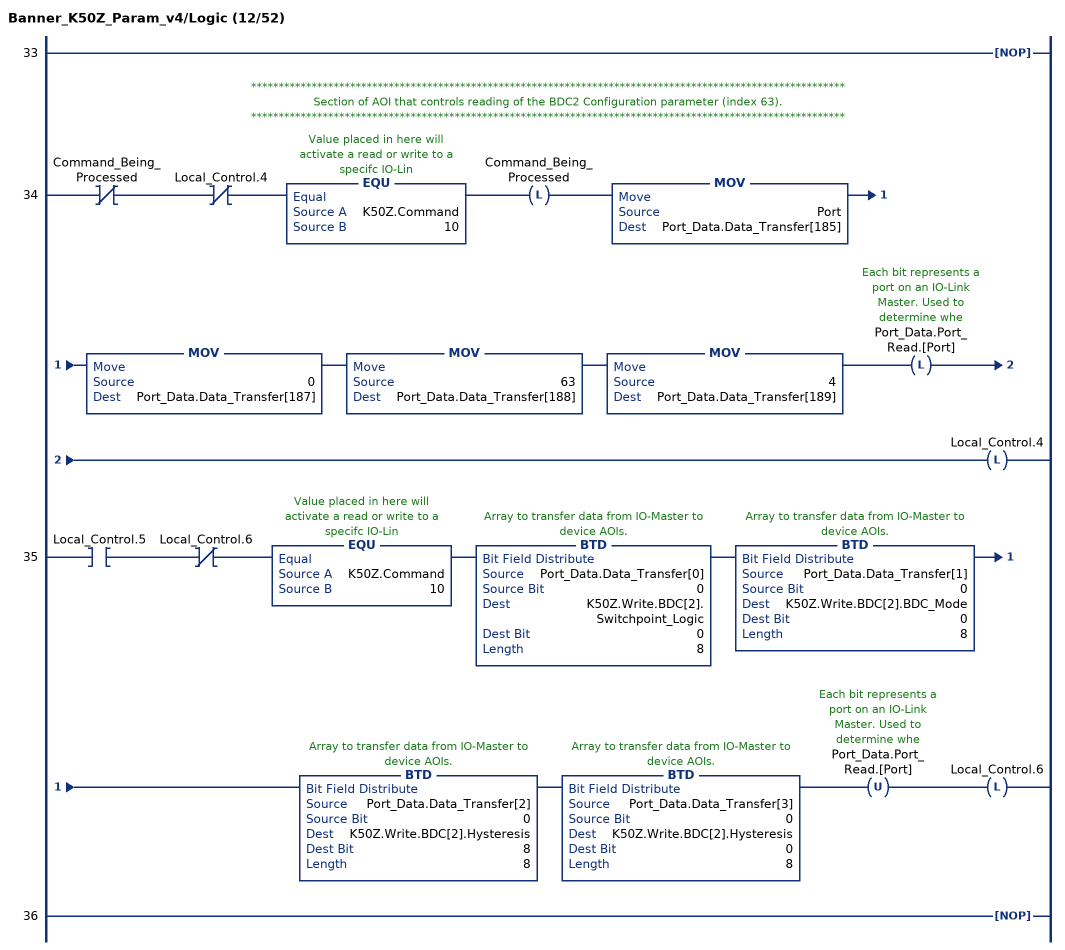
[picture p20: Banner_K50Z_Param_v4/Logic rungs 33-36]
   33: NOP();
   // ************************************************************************************************************
   // Section of AOI that controls reading of the BDC2 Configuration parameter (index 63).
   // ************************************************************************************************************
   34: XIO(Command_Being_Processed)XIO(Local_Control.4)EQU(K50Z.Command,10)OTL(Command_Being_Processed)MOV(Port,Port_Data.Data_Transfer[185])MOV(0,Port_Data.Data_Transfer[187])MOV(63,Port_Data.Data_Transfer[188])MOV(4,Port_Data.Data_Transfer[189])OTL(Port_Data.Port_Read.[Port])OTL(Local_Control.4);
   35: XIC(Local_Control.5)XIO(Local_Control.6)EQU(K50Z.Command,10)BTD(Port_Data.Data_Transfer[0],0,K50Z.Write.BDC[2].Switchpoint_Logic,0,8)BTD(Port_Data.Data_Transfer[1],0,K50Z.Write.BDC[2].BDC_Mode,0,8)BTD(Port_Data.Data_Transfer[2],0,K50Z.Write.BDC[2].Hysteresis,8,8)BTD(Port_Data.Data_Transfer[3],0,K50Z.Write.BDC[2].Hysteresis,0,8)OTU(Port_Data.Port_Read.[Port])OTL(Local_Control.6);
   36: NOP();
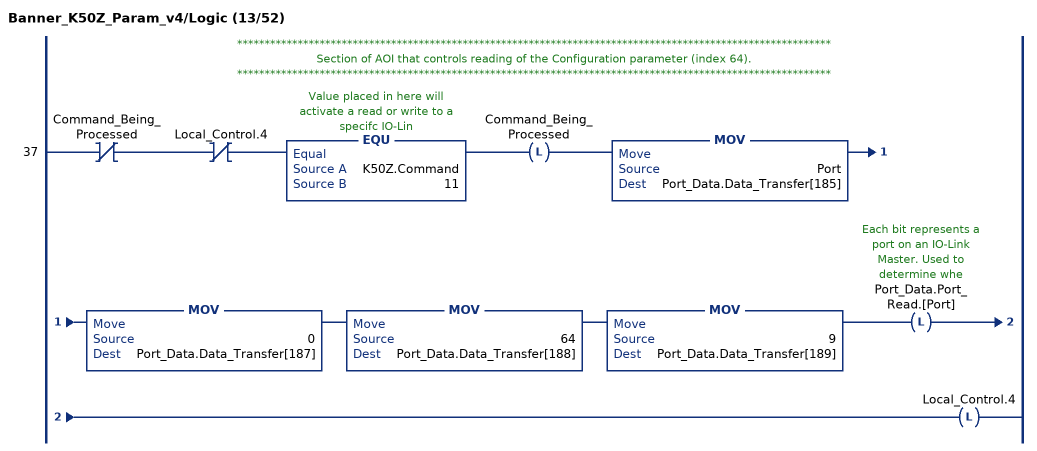
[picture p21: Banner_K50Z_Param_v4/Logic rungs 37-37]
   // ************************************************************************************************************
   // Section of AOI that controls reading of the Configuration parameter (index 64).
   // ************************************************************************************************************
   37: XIO(Command_Being_Processed)XIO(Local_Control.4)EQU(K50Z.Command,11)OTL(Command_Being_Processed)MOV(Port,Port_Data.Data_Transfer[185])MOV(0,Port_Data.Data_Transfer[187])MOV(64,Port_Data.Data_Transfer[188])MOV(9,Port_Data.Data_Transfer[189])OTL(Port_Data.Port_Read.[Port])OTL(Local_Control.4);
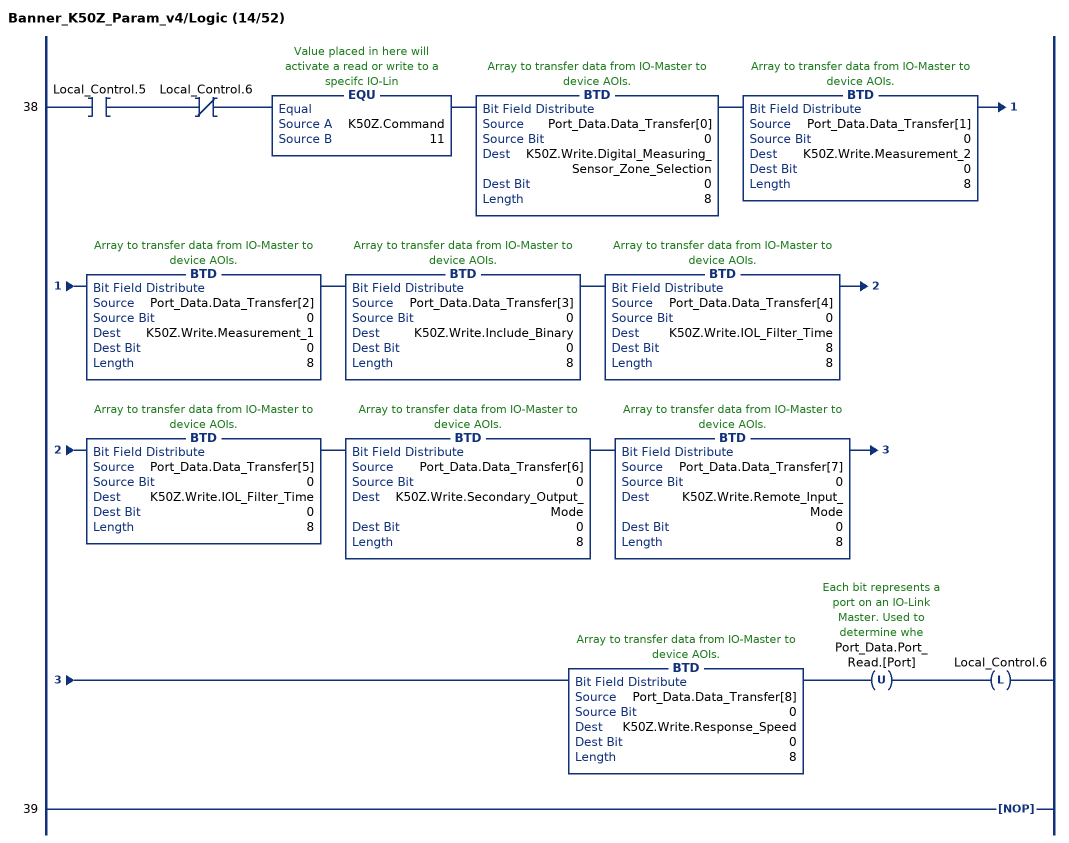
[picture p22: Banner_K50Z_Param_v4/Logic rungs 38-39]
   38: XIC(Local_Control.5)XIO(Local_Control.6)EQU(K50Z.Command,11)BTD(Port_Data.Data_Transfer[0],0,K50Z.Write.Digital_Measuring_Sensor_Zone_Selection,0,8)BTD(Port_Data.Data_Transfer[1],0,K50Z.Write.Measurement_2,0,8)BTD(Port_Data.Data_Transfer[2],0,K50Z.Write.Measurement_1,0,8)BTD(Port_Data.Data_Transfer[3],0,K50Z.Write.Include_Binary,0,8)BTD(Port_Data.Data_Transfer[4],0,K50Z.Write.IOL_Filter_Time,8,8)BTD(Port_Data.Data_Transfer[5],0,K50Z.Write.IOL_Filter_Time,0,8)BTD(Port_Data.Data_Transfer[6],0,K50Z.Write.Secondary_Output_Mode,0,8)BTD(Port_Data.Data_Transfer[7],0,K50Z.Write.Remote_Input_Mode,0,8)BTD(Port_Data.Data_Transfer[8],0,K50Z.Write.Response_Speed,0,8)OTU(Port_Data.Port_Read.[Port])OTL(Local_Control.6);
   39: NOP();
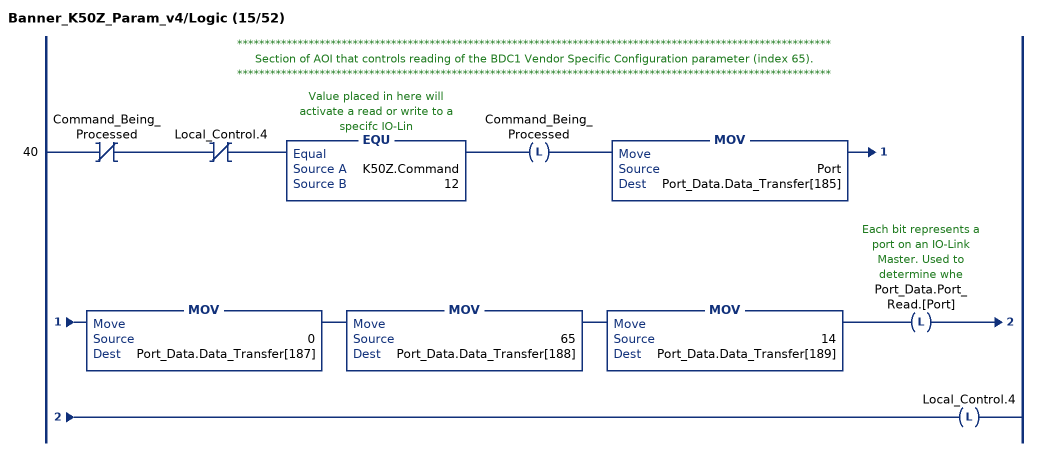
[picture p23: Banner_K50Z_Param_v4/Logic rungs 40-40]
   // ************************************************************************************************************
   // Section of AOI that controls reading of the BDC1 Vendor Specific Configuration parameter (index 65).
   // ************************************************************************************************************
   40: XIO(Command_Being_Processed)XIO(Local_Control.4)EQU(K50Z.Command,12)OTL(Command_Being_Processed)MOV(Port,Port_Data.Data_Transfer[185])MOV(0,Port_Data.Data_Transfer[187])MOV(65,Port_Data.Data_Transfer[188])MOV(14,Port_Data.Data_Transfer[189])OTL(Port_Data.Port_Read.[Port])OTL(Local_Control.4);
